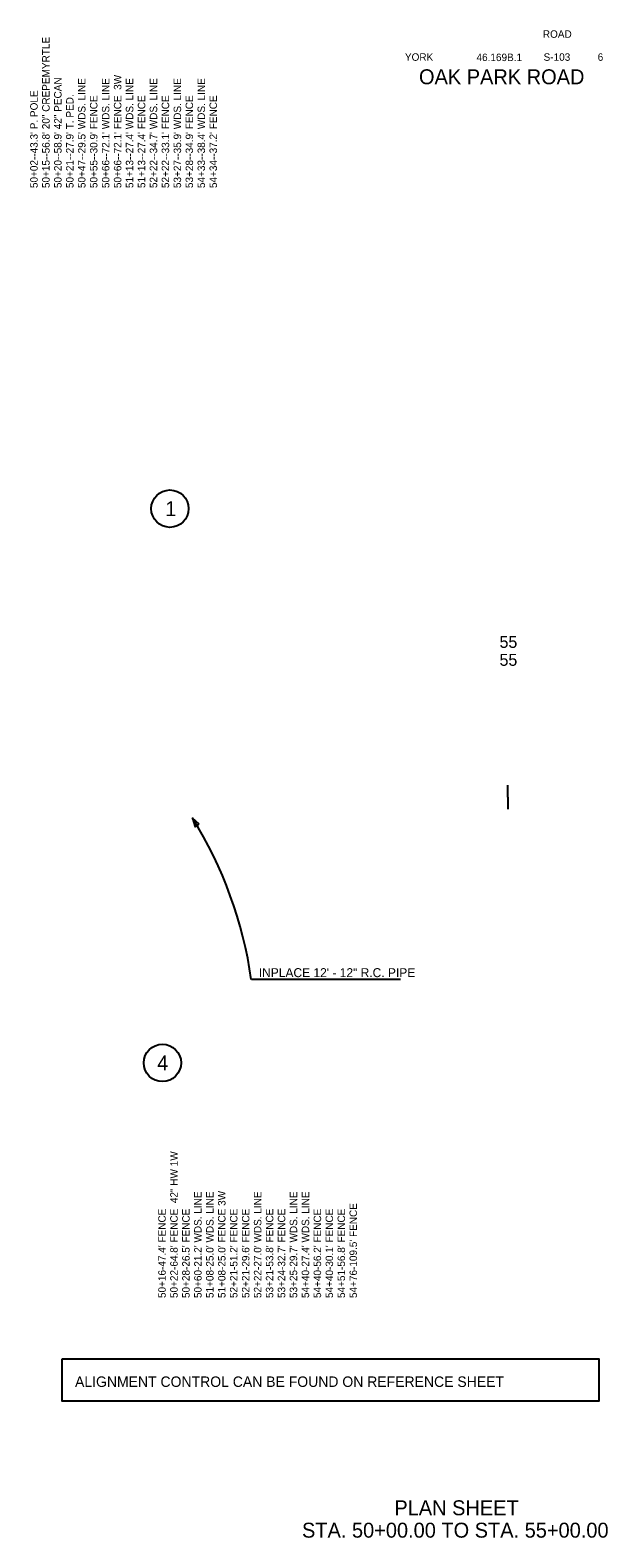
# Model space of a CAD drawing. Extents: x 1964853 to 1967410, y 1117103 to 1120421.
# Drawn here: x 1967024 to 1967410, y 1117103 to 1118112 of the extents above; entities that cross this region are included whole.
import ezdxf

# ---------------------------------------------------------------- set-up
doc = ezdxf.new("R2010")
doc.units = 0
for name, color, linetype in [('Level 1', 7, 'Continuous'), ('Level 12', 7, 'Continuous'), ('Level 19', 7, 'Continuous'), ('Level 21', 7, 'Continuous'), ('Level 24', 7, 'Continuous'), ('Level 25', 7, 'Continuous'), ('Level 26', 7, 'Continuous'), ('Level 41', 7, 'Continuous')]:
    doc.layers.add(name, color=color, linetype=linetype)

msp = doc.modelspace()

# ---------------------------------------------------------------- linework, layer by layer
at = {"layer": 'Level 1'}
for q in [(1967343.5, 1117606.6), (1967343.5, 1117590.6)]:
    msp.add_line((1967343.5, 1117598.6), q, dxfattribs=at)
at = {"layer": 'Level 12'}
for centre in [(1967117.3, 1117791.8), (1967112.3, 1117420.8)]:
    msp.add_circle(centre, 12.5, dxfattribs=at)
at = {"layer": 'Level 25'}
msp.add_lwpolyline([(1967045.2, 1117222.8), (1967404.3, 1117222.8), (1967404.3, 1117194.4), (1967045.2, 1117194.4)], close=True, dxfattribs=at)
at = {"layer": 'Level 26'}
msp.add_line((1967271.7, 1117476.7), (1967171.8, 1117476.7), dxfattribs=at)
msp.add_lwpolyline([(1967136.8, 1117580.6), (1967132.5, 1117584.7), (1967134.2, 1117578.9)], close=True, dxfattribs=at)
msp.add_arc((1966897, 1117437.7), 277.5, 8.0722, 31.9738, dxfattribs=at)

# ---------------------------------------------------------------- texts
at = {"layer": 'Level 12'}
for s, p in [('1', (1967114.2, 1117786.8)), ('4', (1967108.8, 1117415.8))]:
    msp.add_text(s, height=10, dxfattribs=at).set_placement(p)
at = {"layer": 'Level 19'}
msp.add_text('55', height=8, rotation=360, dxfattribs=at).set_placement((1967337.9, 1117698.6))
at = {"layer": 'Level 21'}
msp.add_text('55', height=8, rotation=360, dxfattribs=at).set_placement((1967337.9, 1117686.6))
at = {"layer": 'Level 24'}
for s, p in [('50+15--56.8\' 20" CREPEMYRTLE ', (1967036.8, 1118006.4)), ('50+20--58.9\' 42" PECAN ', (1967044.8, 1118006.4)), ("50+47--29.5' WDS. LINE", (1967060.8, 1118006.4)), ("50+66--72.1' WDS. LINE", (1967076.8, 1118006.4)), ("50+66--72.1' FENCE  3W ", (1967084.8, 1118006.4)), ("51+13--27.4' WDS. LINE", (1967092.8, 1118006.4)), ("52+22--34.7' WDS. LINE", (1967108.8, 1118006.4)), ("53+27--35.9' WDS. LINE", (1967124.8, 1118006.4)), ("54+33--38.4' WDS. LINE", (1967140.8, 1118006.4)), ("50+02--43.3' P. POLE  ", (1967028.8, 1118006.4)), ("50+21--27.9' T. PED.  ", (1967052.8, 1118006.4)), ("50+55--30.9' FENCE  ", (1967068.8, 1118006.4)), ("51+13--27.4' FENCE  ", (1967100.8, 1118006.4)), ("52+22--33.1' FENCE  ", (1967116.8, 1118006.4)), ("53+28--34.9' FENCE  ", (1967132.8, 1118006.4)), ("54+34--37.2' FENCE  ", (1967148.8, 1118006.4)), ('50+22-64.8\' FENCE  42" HW 1W ', (1967122.5, 1117263.4)), ("50+60-21.2' WDS. LINE", (1967138.5, 1117263.4)), ("51+08-25.0' WDS. LINE", (1967146.5, 1117263.4)), ("51+08-25.0' FENCE 3W ", (1967154.5, 1117263.4)), ("52+22-27.0' WDS. LINE", (1967178.5, 1117263.4)), ("53+25-29.7' WDS. LINE", (1967202.5, 1117263.4)), ("54+40-27.4' WDS. LINE", (1967210.5, 1117263.4)), ("50+16-47.4' FENCE  ", (1967114.5, 1117263.4)), ("50+28-26.5' FENCE  ", (1967130.5, 1117263.4)), ("52+21-51.2' FENCE  ", (1967162.5, 1117263.4)), ("52+21-29.6' FENCE  ", (1967170.5, 1117263.4)), ("53+21-53.8' FENCE  ", (1967186.5, 1117263.4)), ("53+24-32.7' FENCE  ", (1967194.5, 1117263.4)), ("54+40-56.2' FENCE  ", (1967218.5, 1117263.4)), ("54+40-30.1' FENCE  ", (1967226.5, 1117263.4)), ("54+51-56.8' FENCE  ", (1967234.5, 1117263.4)), ("54+76-109.5' FENCE  ", (1967242.5, 1117263.4))]:
    msp.add_text(s, height=5, rotation=90, dxfattribs=at).set_placement(p)
at = {"layer": 'Level 25'}
msp.add_text('ALIGNMENT CONTROL CAN BE FOUND ON REFERENCE SHEET', height=7, dxfattribs=at).set_placement((1967053.8, 1117203.9))
at = {"layer": 'Level 26'}
msp.add_text('INPLACE 12\' - 12" R.C. PIPE', height=6, dxfattribs=at).set_placement((1967176.8, 1117478.2))
at = {"layer": 'Level 41'}
for s, height, p in [('ROAD', 5, (1967366.9, 1118107)), ('YORK', 5, (1967274.6, 1118091.6)), ('46.169B.1', 5, (1967322.5, 1118091.4)), ('S-103', 5, (1967367.4, 1118091.6)), ('6', 5, (1967403.6, 1118091.6)), ('OAK PARK ROAD', 10, (1967284, 1118075.9)), ('PLAN SHEET', 10, (1967267.5, 1117118)), ('STA. 50+00.00 TO STA. 55+00.00', 10, (1967205.7, 1117103))]:
    msp.add_text(s, height=height, dxfattribs=at).set_placement(p)

doc.saveas('drawing.dxf')
